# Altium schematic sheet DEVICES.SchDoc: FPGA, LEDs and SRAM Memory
size A4; Organization: Altium Limited.; Address1: Level 3, 12a Rodborough Rd; Address2: Frenchs Forest 2086; Address3: NSW; Address4: AUSTRALIA; DocumentNumber: 2; SheetNumber: 3; SheetTotal: 23
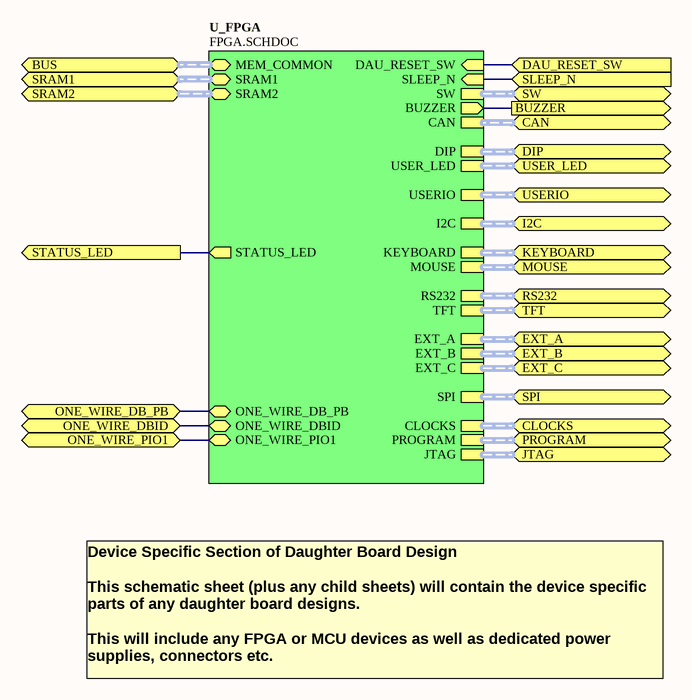
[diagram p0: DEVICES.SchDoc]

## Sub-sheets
U_FPGA = FPGA.SCHDOC: SRAM1 (harness SRAM-256Kx16), SRAM2 (harness SRAM-256Kx16), MEM_COMMON (harness HOSTMEMORY), DAU_RESET_SW (in), BUZZER (out), ONE_WIRE_DBID (bidir), ONE_WIRE_DB_PB (bidir), ONE_WIRE_PIO1 (bidir), JTAG (harness HardSoft_JTAG), SW (harness SW5), DIP (harness SW8), USERIO (harness IO36), EXT_A (harness PBIO), EXT_B (harness PBIO), EXT_C (harness PBIO), USER_LED (harness LED8), SPI (harness DAU_SPI), I2C (harness I2C), CAN (harness CAN_INT), RS232 (harness RS232_INT), KEYBOARD (harness PS2), MOUSE (harness PS2), TFT (harness DAU_TFT), PROGRAM (harness DAU_CTRL), CLOCKS (harness DAU_CLK), STATUS_LED (out), SLEEP_N (in)

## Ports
BUS (harness HOSTMEMORY), BUZZER (out), CAN, CLOCKS, DAU_RESET_SW (in), DIP, EXT_A, EXT_B, EXT_C, I2C, JTAG, KEYBOARD, MOUSE, ONE_WIRE_DB_PB (bidir), ONE_WIRE_DBID (bidir), ONE_WIRE_PIO1 (bidir), PROGRAM, RS232, SLEEP_N (in), SPI, SRAM1, SRAM2 (harness SRAM-256Kx16), STATUS_LED (out), SW, TFT, USER_LED, USERIO

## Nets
BUZZER: port BUZZER, sheet U_FPGA/BUZZER
DAU_RESET_SW: port DAU_RESET_SW, sheet U_FPGA/DAU_RESET_SW
ONE_WIRE_DB_PB: port ONE_WIRE_DB_PB, sheet U_FPGA/ONE_WIRE_DB_PB
ONE_WIRE_DBID: port ONE_WIRE_DBID, sheet U_FPGA/ONE_WIRE_DBID
ONE_WIRE_PIO1: port ONE_WIRE_PIO1, sheet U_FPGA/ONE_WIRE_PIO1
SLEEP_N: port SLEEP_N, sheet U_FPGA/SLEEP_N
STATUS_LED: port STATUS_LED, sheet U_FPGA/STATUS_LED

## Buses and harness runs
harness port BUS = sheet U_FPGA/MEM_COMMON
harness port CAN = sheet U_FPGA/CAN
harness port CLOCKS = sheet U_FPGA/CLOCKS
harness port DIP = sheet U_FPGA/DIP
harness port EXT_A = sheet U_FPGA/EXT_A
harness port EXT_B = sheet U_FPGA/EXT_B
harness port EXT_C = sheet U_FPGA/EXT_C
harness port I2C = sheet U_FPGA/I2C
harness port JTAG = sheet U_FPGA/JTAG
harness port KEYBOARD = sheet U_FPGA/KEYBOARD
harness port MOUSE = sheet U_FPGA/MOUSE
harness port PROGRAM = sheet U_FPGA/PROGRAM
harness port RS232 = sheet U_FPGA/RS232
harness port SPI = sheet U_FPGA/SPI
harness port SRAM1 = sheet U_FPGA/SRAM1
harness port SRAM2 = sheet U_FPGA/SRAM2
harness port SW = sheet U_FPGA/SW
harness port TFT = sheet U_FPGA/TFT
harness port USER_LED = sheet U_FPGA/USER_LED
harness port USERIO = sheet U_FPGA/USERIO

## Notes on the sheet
- Device Specific Section of Daughter Board Design
  This schematic sheet (plus any child sheets) will contain the device specific parts of any daughter board designs.
  This will include any FPGA or MCU devices as well as dedicated power supplies, connectors etc.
